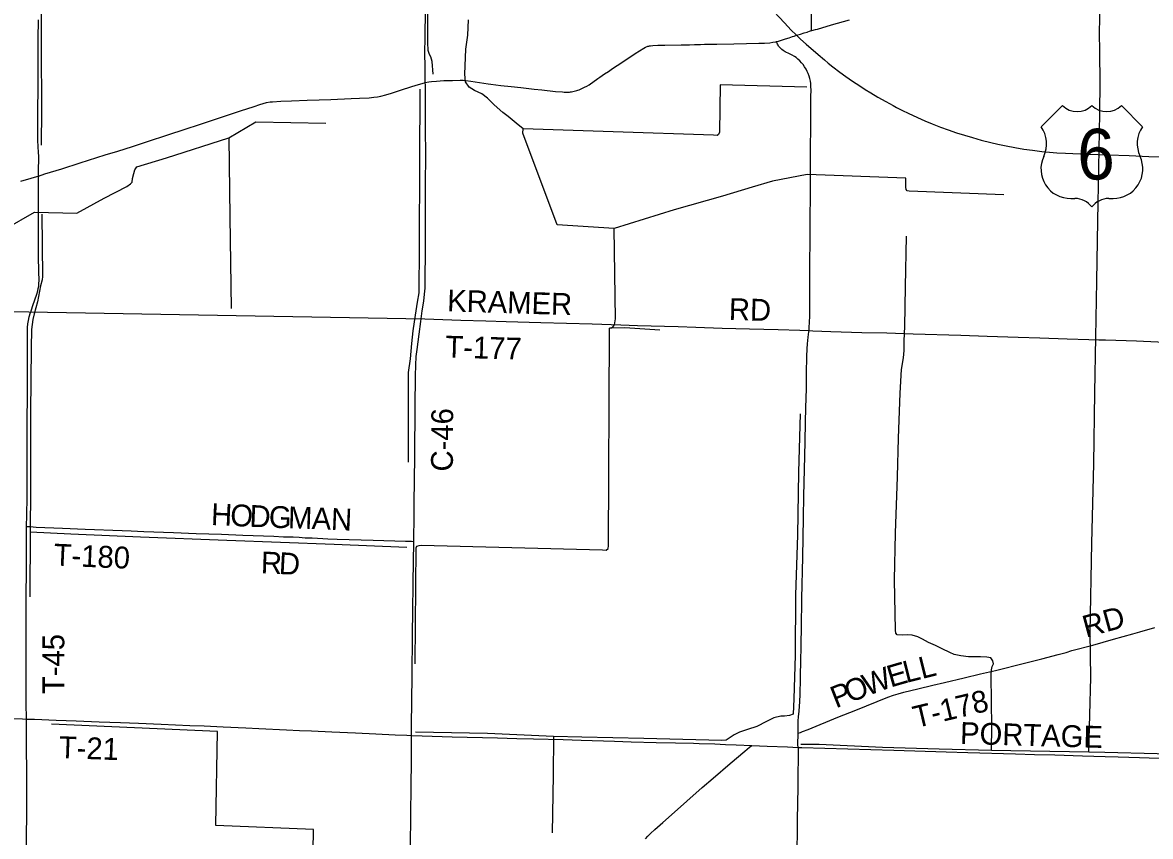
# Model space of a CAD drawing. Extents: x 0 to 680, y 0 to 834.
# Drawn here: x 187.9 to 300.6, y 223.2 to 304.5 of the extents above; entities that cross this region are included whole.
import ezdxf

# ---------------------------------------------------------------- set-up
doc = ezdxf.new("R2010")
doc.units = 0
for name, color, linetype in [('GM_X_County_Road', 7, 'Continuous'), ('GM_X_County_Road_Text', 7, 'Continuous'), ('GM_X_Minor_River', 7, 'Continuous'), ('GM_X_Township_Road', 7, 'Continuous'), ('GM_X_Township_Road_Text', 7, 'Continuous'), ('GM_X_US_Location', 7, 'Continuous'), ('GM_X_US_Route', 7, 'Continuous'), ('GM_X_US_Shield', 7, 'Continuous')]:
    doc.layers.add(name, color=color, linetype=linetype)

msp = doc.modelspace()

# ---------------------------------------------------------------- linework, layer by layer
at = {"layer": 'GM_X_County_Road'}
for points in [[(228.18, 298.27), (228.17, 298.53), (228.17, 298.79), (228.15, 299.46), (228.14, 300.18), (228.13, 301.37), (228.15, 303.16), (228.19, 305.66), (228.22, 309.12), (228.23, 310.91), (228.25, 314.73), (228.31, 320.34), (228.35, 323.92), (228.39, 326.54), (228.42, 328.93), (228.45, 332.36)], [(266.76, 303.71), (266.8, 303.72), (267.17, 303.82), (267.35, 303.87), (268.76, 304.28), (269.34, 304.44), (270.56, 304.78)], [(264.86, 303.11), (265.01, 303.17), (265.27, 303.25)], [(265.27, 303.25), (265.66, 303.37), (266.03, 303.48), (266.32, 303.57)], [(266.32, 303.57), (266.39, 303.6), (266.57, 303.65), (266.76, 303.71)], [(228.17, 298.53), (228.51, 298.58), (228.78, 298.63), (229.28, 298.67), (230.03, 298.71), (230.88, 298.74), (231.66, 298.75), (231.95, 298.75), (232.21, 298.73), (232.73, 298.66), (234.45, 298.4), (234.73, 298.36), (235.73, 298.23), (236.75, 298.12), (237.7, 298.02), (239.03, 297.87), (239.81, 297.79), (241.19, 297.64), (241.88, 297.58), (242.04, 297.56), (242.16, 297.56), (242.36, 297.56), (242.57, 297.57), (242.69, 297.58), (242.79, 297.6), (242.91, 297.62), (243.03, 297.65), (243.17, 297.68), (243.3, 297.73), (243.42, 297.76), (243.53, 297.8), (243.68, 297.86), (243.82, 297.92), (244.08, 298.05), (244.31, 298.17), (244.54, 298.31), (245.4, 298.91), (245.62, 299.06), (246.09, 299.38), (246.46, 299.64), (246.87, 299.92), (247.35, 300.24), (248.7, 301.13), (249.14, 301.43), (249.99, 301.96), (250.16, 302.04), (250.32, 302.11), (250.41, 302.15), (250.49, 302.17), (250.58, 302.19), (250.68, 302.2), (250.91, 302.22), (251.39, 302.24), (252.11, 302.25), (253.73, 302.28), (254.55, 302.3), (255.05, 302.32), (255.65, 302.33), (256.08, 302.34), (256.7, 302.35), (257.29, 302.36), (258.99, 302.39), (260.27, 302.41), (261.5, 302.44), (262.07, 302.45), (262.59, 302.5), (262.9, 302.54), (263.2, 302.6), (263.27, 302.61)], [(263.27, 302.61), (263.46, 302.66), (263.76, 302.75), (264.16, 302.88)], [(264.16, 302.88), (264.51, 302.99), (264.86, 303.11)], [(189.51, 289.18), (190.16, 289.39), (191.87, 289.92), (193.69, 290.49), (196.19, 291.3), (197.45, 291.68), (198.93, 292.15), (199.5, 292.33), (200.52, 292.66), (202.33, 293.26), (204.26, 293.9), (205.51, 294.3), (206.42, 294.6), (207.32, 294.9), (209.7, 295.69), (211.07, 296.13), (211.63, 296.33), (211.97, 296.44), (212.31, 296.52), (212.66, 296.58), (212.9, 296.6), (213.73, 296.65), (214.8, 296.69), (216.36, 296.75), (217.55, 296.8), (218.74, 296.84), (220.77, 296.92), (221.6, 296.96), (222.56, 297), (223.03, 297.05), (223.39, 297.1), (223.74, 297.17), (224.21, 297.28), (224.78, 297.45), (225.69, 297.75), (226.82, 298.13), (227.5, 298.34), (228.08, 298.5), (228.17, 298.53)], [(227.72, 274.66), (227.76, 274.93), (227.87, 275.73), (228.01, 276.68), (228.09, 277.39), (228.14, 277.99), (228.17, 278.58), (228.17, 279.54), (228.18, 280.97), (228.18, 281.92), (228.19, 283.59), (228.19, 284.07), (228.18, 284.55), (228.19, 285.14), (228.2, 286.81), (228.2, 288.13), (228.21, 291.47), (228.2, 293.73), (228.2, 295.05), (228.2, 295.88), (228.2, 296.84), (228.18, 298.27)], [(187.76, 288.66), (188.8, 288.96), (189.37, 289.13), (189.51, 289.18)], [(227.01, 252.42), (227.02, 252.69), (227.02, 253.13), (227.05, 254.92), (227.07, 256.59), (227.1, 258.74), (227.12, 261.24), (227.16, 266.14), (227.19, 269.24), (227.22, 270.31), (227.27, 271.15), (227.34, 271.86), (227.54, 273.4), (227.72, 274.66)], [(226.79, 233.07), (226.79, 233.32), (226.79, 234.27), (226.82, 236.78), (226.84, 239.28), (226.89, 243.34), (226.98, 250.86), (227.01, 252.42)], [(226.65, 196.73), (226.64, 197), (226.64, 197.27), (226.63, 199.18), (226.61, 200.97), (226.62, 203.36), (226.65, 207.65), (226.67, 210.52), (226.66, 213.74), (226.66, 214.93), (226.66, 216.61), (226.67, 219.59), (226.69, 222.34), (226.72, 225.2), (226.77, 228.42), (226.78, 230.57), (226.79, 232.96), (226.79, 233.07)]]:
    msp.add_lwpolyline(points, dxfattribs=at)
at = {"layer": 'GM_X_Minor_River'}
for points in [[(228.96, 299.35), (228.86, 300.64), (228.73, 301.09), (228.6, 301.34), (228.46, 301.73), (228.42, 302.53), (228.42, 313.14), (228.74, 324.28), (228.83, 333.5), (228.87, 343.1), (228.89, 347.61), (228.91, 352.15), (228.94, 355.48), (228.93, 357.36), (228.06, 357.4), (223.98, 357.49), (220.6, 357.57)], [(189.84, 314.17), (189.8, 309.14), (189.79, 302.09), (189.81, 295.76), (189.8, 292.27)], [(294.45, 231.64), (294.65, 239.1), (294.59, 243.59), (294.76, 252.52), (294.96, 260.45), (295.07, 267.55), (295.17, 273.08), (295.26, 278.7), (295.35, 284.71), (295.47, 290.05), (295.56, 295.43), (295.61, 298.58), (295.55, 301.5), (295.54, 303.62), (295.59, 306.02), (295.6, 308.36)], [(266.3, 298.07), (257.63, 298.28), (257.57, 293.55), (257.48, 293.34), (257.32, 293.24), (256.96, 293.26), (246.95, 293.6), (237.95, 293.91), (237.26, 294.48), (236.46, 295.14), (235.93, 295.54), (235.06, 296.31), (234.4, 296.97), (233.83, 297.38), (233.08, 297.74), (232.55, 298.06), (232.18, 298.58), (232.12, 299.37), (232.23, 301.87), (232.41, 303.27), (232.47, 304.8)], [(227.61, 297.87), (227.59, 290.69), (227.54, 282.11), (227.52, 277.52), (227.35, 276.58), (227.15, 275.29), (226.92, 273.73), (226.78, 272.47), (226.66, 270.94), (226.47, 269.55), (226.45, 260.6)], [(186.24, 283.92), (189.11, 285.56), (193.35, 285.48), (196.07, 286.99), (198.36, 288.15), (198.72, 288.4), (198.87, 288.58), (198.93, 288.93), (199.05, 289.44), (199.14, 289.82), (199.36, 290.1), (202.32, 291), (208.53, 292.99), (211.23, 294.6), (218.24, 294.48)], [(285.98, 287.31), (276.51, 287.67), (276.33, 287.71), (276.22, 287.83), (276.19, 288.06), (276.18, 288.98), (266.31, 289.34), (262.86, 288.67), (260.83, 288.07), (257.86, 287.19), (253.03, 285.8), (247.05, 283.94), (241.34, 284.3), (237.93, 293.48), (237.95, 293.91)], [(208.53, 292.99), (208.64, 285.11), (208.78, 275.94)], [(189.87, 285.39), (189.91, 279.14), (189.89, 278.82), (189.72, 278.21), (189.42, 276.63), (189.1, 275.41), (188.94, 274.87), (188.89, 274.36), (188.83, 273.85), (188.78, 272.03), (188.72, 265.56), (188.71, 257.88), (188.68, 253.65), (188.65, 247.17)], [(246.77, 274.02), (246.95, 274.15), (247.08, 274.33), (247.17, 274.92), (247.05, 283.94)], [(284.73, 231.8), (284.78, 234.23), (284.75, 236.63), (284.71, 239.37), (284.74, 239.86), (284.81, 240.19), (284.93, 240.47), (284.89, 240.76), (284.66, 241.05), (284.28, 241.14), (283.64, 241.17), (282.43, 241.15), (281.66, 241.25), (281, 241.41), (280.58, 241.6), (279.81, 241.97), (279.14, 242.29), (278.45, 242.6), (277.84, 242.94), (277.38, 243.16), (276.83, 243.34), (276.34, 243.35), (275.82, 243.33), (275.32, 243.37), (275.18, 243.52), (275.14, 243.81), (275.04, 248.84), (275.14, 253.52), (275.36, 259.15), (275.44, 263), (275.63, 267.51), (275.76, 269.85), (275.96, 271.04), (276.01, 271.76), (276.03, 272.72), (276.07, 274.15), (276.16, 278.13), (276.26, 283.19)], [(227.15, 240.45), (227.27, 252.06), (227.33, 252.22), (227.56, 252.29), (227.75, 252.31), (245.89, 251.86), (246.24, 251.83), (246.43, 251.98), (246.48, 252.25), (246.57, 273.7), (246.57, 273.99), (246.64, 274.02), (246.77, 274.02), (248.09, 274.07), (251.61, 273.81)], [(265.62, 265.44), (265.47, 259.62), (265.36, 253.31), (265.15, 247.34), (265.12, 241.32), (264.99, 236.97), (264.93, 235.42), (264.56, 235.29), (264.07, 235.24), (263.69, 235.22), (262.99, 235.08), (262.26, 234.69), (261.28, 234.22), (260.35, 233.91), (259.57, 233.65), (259.02, 233.37), (258.22, 232.85), (257.81, 232.82), (250.01, 232.99), (243.81, 233.14), (240.98, 233.22), (234.4, 233.5), (227.19, 233.65)], [(188.68, 253.65), (192.75, 253.46), (199.7, 253.16), (208.35, 252.82), (219.06, 252.41), (226.31, 252.12)], [(328.62, 238.69), (328.67, 234.36), (328.71, 230.59), (323.47, 230.8), (316.16, 231.05), (308.68, 231.28), (304.59, 231.37), (301.3, 231.48), (296.08, 231.6), (294.45, 231.64), (284.73, 231.8), (279.51, 231.95), (273.85, 232.09), (267.51, 232.41), (265.69, 232.42)], [(225.69, 156.4), (225.77, 161.71), (225.82, 168.08), (225.67, 173.03), (225.8, 175.83), (226.05, 186.97), (226.14, 191.99), (226.1, 194.92), (226.09, 209.74), (226.16, 218.33), (226.11, 218.56), (225.98, 218.74), (225.77, 218.78), (224.97, 218.81), (217.54, 219.1), (217.23, 219.13), (217.09, 219.21), (216.94, 219.61), (217, 223.9), (207.23, 224.33), (207.42, 233.72), (190.81, 234.44)], [(240.98, 233.22), (240.94, 229.35), (240.85, 223.59)]]:
    msp.add_lwpolyline(points, dxfattribs=at)
at = {"layer": 'GM_X_Township_Road'}
msp.add_line((188.74, 275.6), (188.91, 276.14), dxfattribs=at)
for points in [[(266.76, 303.71), (266.76, 303.9), (266.76, 305.17), (266.78, 306.5), (266.78, 307.62), (266.78, 308.43), (266.8, 310.44), (266.81, 312.08)], [(189.51, 289.18), (189.51, 289.39), (189.52, 289.86), (189.55, 290.82), (189.55, 291.18), (189.53, 291.53), (189.48, 292.13), (189.45, 292.72), (189.45, 293.44), (189.47, 295.23), (189.48, 298.46), (189.49, 302.88), (189.51, 304.79)], [(264.86, 303.11), (265.01, 303.17), (265.27, 303.25)], [(265.27, 303.25), (265.66, 303.37), (266.03, 303.48), (266.32, 303.57)], [(266.32, 303.57), (266.39, 303.6), (266.57, 303.65), (266.76, 303.71)], [(263.27, 302.61), (263.46, 302.66), (263.76, 302.75), (264.16, 302.88)], [(266.7, 297.19), (266.71, 297.7), (266.69, 298.19), (266.68, 298.43), (266.64, 298.66), (266.59, 298.92), (266.51, 299.17), (266.43, 299.42), (266.33, 299.64), (266.21, 299.87), (266.07, 300.1), (265.92, 300.31), (265.76, 300.49), (265.59, 300.68), (265.39, 300.86), (265.21, 301.01), (265.05, 301.12), (264.83, 301.26), (264.55, 301.4), (264.14, 301.6), (263.94, 301.72), (263.78, 301.83), (263.65, 301.94), (263.56, 302.04), (263.47, 302.16), (263.41, 302.26), (263.37, 302.37), (263.27, 302.61)], [(264.16, 302.88), (264.51, 302.99), (264.86, 303.11)], [(266.51, 273.75), (266.53, 274.07), (266.55, 274.6), (266.58, 275.2), (266.59, 275.79), (266.6, 277.6), (266.6, 280.45), (266.62, 282.77), (266.63, 284.2), (266.66, 287.99), (266.66, 290), (266.66, 291), (266.67, 292.41), (266.68, 293.61), (266.68, 294.7), (266.69, 296.61), (266.7, 297.19)], [(188.91, 276.14), (188.95, 276.25), (189.35, 277.37), (189.45, 277.72), (189.5, 277.95), (189.55, 278.18), (189.57, 278.42), (189.58, 278.78), (189.57, 279.61), (189.53, 281.17), (189.53, 282.48), (189.52, 285.34), (189.52, 287.61), (189.51, 288.81), (189.51, 289.18)], [(111.24, 276.97), (228.13, 274.92), (231.71, 274.79), (234.22, 274.71), (236.24, 274.65), (239.71, 274.55), (244.84, 274.41), (247.7, 274.32), (249.37, 274.27), (253.42, 274.14), (255.21, 274.08), (257.83, 273.99), (260.57, 273.91), (263.44, 273.84), (265.58, 273.78), (266.51, 273.75)], [(188.33, 254.19), (188.35, 255.31), (188.38, 257.1), (188.39, 259.37), (188.4, 260.92), (188.4, 262.59), (188.4, 264.98), (188.41, 267.01), (188.42, 269.99), (188.41, 272.38), (188.41, 273.45), (188.43, 274.05), (188.46, 274.41), (188.51, 274.76), (188.59, 275.11), (188.72, 275.57), (188.74, 275.6)], [(265.41, 233.55), (265.42, 233.59), (265.43, 234.31), (265.44, 234.76), (265.47, 235.16), (265.53, 235.73), (265.57, 236.23), (265.59, 236.68), (265.62, 237.45), (265.65, 238.97), (265.7, 241.05), (265.72, 241.86), (265.73, 242.74), (265.75, 243.84), (265.76, 244.87), (265.79, 246.18), (265.8, 246.99), (265.88, 251.12), (265.96, 255.05), (266, 257.23), (266.06, 259.86), (266.11, 262.63), (266.16, 264.59), (266.19, 266.04), (266.24, 267.97), (266.27, 269.48), (266.29, 271.17), (266.32, 271.91), (266.36, 272.44), (266.42, 273.08), (266.5, 273.62), (266.51, 273.75)], [(266.51, 273.75), (266.9, 273.73), (268.69, 273.67), (271.79, 273.57), (274.29, 273.51), (276.92, 273.43), (281.69, 273.28), (284.31, 273.2), (287.42, 273.1), (289.56, 273.03), (292.31, 272.94), (294.45, 272.87), (295.46, 272.84)], [(295.46, 272.84), (296.12, 272.81), (299.22, 272.71), (301.37, 272.64), (302.92, 272.59), (304.95, 272.5), (305.2, 272.5)], [(188.31, 234.95), (188.31, 235.02), (188.3, 236.45), (188.3, 238.96), (188.29, 243.13), (188.3, 247.55), (188.32, 249.46), (188.33, 251.85), (188.32, 253.76), (188.33, 254.19)], [(188.33, 254.19), (188.69, 254.17), (189.29, 254.13), (191.91, 254.02), (194.18, 253.93), (197.88, 253.78), (198.77, 253.74)], [(198.77, 253.74), (200.03, 253.69), (203.02, 253.59), (205.29, 253.49), (207.8, 253.4), (209.94, 253.32), (213.05, 253.21), (214, 253.16), (214.96, 253.14), (215.55, 253.1), (216.15, 253.06), (216.87, 253.04), (217.94, 252.98), (218.42, 252.96), (219.37, 252.93), (222.96, 252.8), (226.18, 252.7), (226.66, 252.7), (226.8, 252.7), (227.02, 252.69)], [(265.41, 233.55), (265.64, 233.62), (265.86, 233.7), (266.42, 233.91), (269.4, 235.13), (271.17, 235.85), (274.39, 237.13), (274.95, 237.34), (275.4, 237.48), (275.98, 237.64), (277.37, 237.98), (278.88, 238.32), (280.04, 238.6), (282.02, 239.06), (283.64, 239.46), (285.15, 239.81), (288.05, 240.52), (289.78, 240.97), (291.4, 241.41), (292.2, 241.61), (292.78, 241.78), (294.85, 242.33), (296.92, 242.92), (298.87, 243.46), (299.56, 243.65), (301.05, 244.1)], [(149.45, 236.02), (150.22, 235.98), (153.57, 235.88), (158.1, 235.78), (161.8, 235.68), (163.71, 235.63), (168.13, 235.52), (171.59, 235.42), (173.26, 235.37), (175.41, 235.31), (179.34, 235.2), (181.61, 235.15), (186.62, 235), (187.94, 234.96), (188.31, 234.95)], [(188.15, 196.36), (188.15, 196.7), (188.17, 198.13), (188.17, 200.16), (188.21, 203.74), (188.27, 207.2), (188.29, 209.11), (188.32, 210.9), (188.31, 213.77), (188.31, 215.56), (188.3, 217.59), (188.3, 219.26), (188.31, 220.81), (188.31, 222.72), (188.34, 225.94), (188.35, 227.5), (188.35, 229.88), (188.33, 231.91), (188.32, 233.46), (188.31, 234.95)], [(188.31, 234.95), (189.13, 234.92), (191.28, 234.84), (193.3, 234.77), (195.57, 234.68), (196.65, 234.65), (197.72, 234.61), (199.51, 234.54), (201.77, 234.45), (204.64, 234.31), (206.07, 234.26), (207.98, 234.17), (210.24, 234.06), (211.55, 234), (214.3, 233.88), (215.61, 233.81), (216.8, 233.76), (218.83, 233.67), (221.21, 233.56), (223.24, 233.48), (225.15, 233.38), (226.34, 233.34), (226.79, 233.32)], [(226.79, 233.32), (227.87, 233.28), (230.86, 233.18), (235.39, 233.07), (237.3, 233.02), (238.97, 232.96), (241.95, 232.89), (243.74, 232.83), (247.08, 232.73), (248.74, 232.67), (251.25, 232.62), (253.16, 232.57), (254.95, 232.53), (255.54, 232.51), (257.09, 232.46), (258.17, 232.4), (259.24, 232.36), (260.79, 232.32)], [(265.43, 232.12), (265.41, 232.22), (265.4, 232.28), (265.4, 232.32), (265.4, 232.36), (265.41, 233.55)], [(250.17, 222.99), (250.41, 223.25), (250.66, 223.51), (251.09, 223.92), (251.89, 224.63), (253.06, 225.66), (254.31, 226.76), (255.83, 228.11), (256.92, 229.04), (258.64, 230.52), (260.1, 231.75), (260.56, 232.13), (260.79, 232.32)], [(260.79, 232.32), (262.34, 232.25), (264.36, 232.16), (265.43, 232.12)], [(265.32, 222.02), (265.35, 223.62), (265.37, 224.84), (265.4, 226.56), (265.41, 228.11), (265.44, 229.83), (265.46, 230.64), (265.47, 231.54), (265.47, 231.93), (265.47, 231.96), (265.46, 231.99), (265.46, 232.02), (265.43, 232.12)], [(265.43, 232.12), (265.79, 232.11), (274.98, 231.83), (280.22, 231.66), (282.37, 231.61), (287.14, 231.48), (289.05, 231.42), (291.08, 231.36), (293.82, 231.27), (296.09, 231.2), (297.4, 231.17), (299.54, 231.11), (300.5, 231.08), (301.69, 231.05), (304.08, 230.97), (304.45, 230.96)]]:
    msp.add_lwpolyline(points, dxfattribs=at)
at = {"layer": 'GM_X_US_Route'}
for points in [[(262.5, 306.15), (264.07, 304.48), (264.74, 303.77), (265.21, 303.3), (265.27, 303.25)], [(265.27, 303.25), (265.66, 302.87), (266.23, 302.36), (267.42, 301.31), (268.04, 300.78), (268.42, 300.47), (268.88, 300.1), (269.6, 299.55), (270.2, 299.11), (270.84, 298.67), (271.58, 298.18), (272.13, 297.83), (272.67, 297.5), (273.39, 297.07), (274.17, 296.62), (274.91, 296.22), (275.26, 296.04), (275.86, 295.74), (276.42, 295.46), (277.35, 295.03), (278.07, 294.71), (278.82, 294.39), (279.64, 294.07), (280.42, 293.79), (281.24, 293.51), (282.03, 293.26), (282.83, 293.02), (283.71, 292.78), (284.66, 292.54), (285.38, 292.37), (286.19, 292.2), (287.08, 292.03), (287.98, 291.88), (288.83, 291.76), (289.77, 291.64), (290.53, 291.57), (291.27, 291.51), (292.15, 291.46), (294.37, 291.37), (296.4, 291.29), (298.5, 291.22), (300.45, 291.14), (301.79, 291.09)]]:
    msp.add_lwpolyline(points, dxfattribs=at)
at = {"layer": 'GM_X_US_Shield'}
for p, q in [((291.82, 296.22), (289.71, 294.11)), ((299.83, 294.11), (297.73, 296.22)), ((292.66, 286.94), (293.08, 286.94)), ((296.46, 286.94), (296.88, 286.94))]:
    msp.add_line(p, q, dxfattribs=at)
for centre, radius, start, end in [((293.3, 297.73), 2.11, 225.573, 314.427), ((296.25, 297.73), 2.11, 225.573, 314.427), ((287.29, 292.42), 2.95, 334.5471, 35.0009), ((302.25, 292.42), 2.95, 144.9991, 205.4529), ((292.63, 289.89), 2.95, 154.8319, 270.6383), ((296.91, 289.89), 2.95, 269.3617, 25.1681), ((293.08, 284.83), 2.11, 36.8699, 90), ((296.46, 284.83), 2.11, 90, 143.1301)]:
    msp.add_arc(centre, radius, start, end, dxfattribs=at)

# ---------------------------------------------------------------- texts
at = {"layer": 'GM_X_County_Road_Text'}
msp.add_text('C-46', height=2.182, rotation=89.6587, dxfattribs=at).set_placement((230.92, 259.67))
at = {"layer": 'GM_X_Township_Road_Text'}
for s, height, rotation, p in [('KRAMER', 2.182, 358.2397, (230.33, 275.67)), ('RD', 2.182, 358.5193, (258.48, 274.81)), ('T-177', 2.182, 358.3265, (230.15, 271.06)), ('H', 2.18, 357.5003, (206.73, 254.33)), ('O', 2.18, 357.4967, (208.65, 254.24)), ('D', 2.18, 357.5024, (210.57, 254.16)), ('G', 2.18, 358.024, (212.51, 254.07)), ('M', 2.18, 358.1903, (214.43, 254.01)), ('A', 2.18, 357.6388, (216.79, 253.93)), ('N', 2.18, 357.6315, (218.71, 253.85)), ('T-180', 2.182, 357.4726, (191, 250.29)), ('R', 2.18, 358.2239, (211.72, 249.5)), ('D', 2.18, 356.9933, (213.5, 249.44)), ('RD', 2.182, 15.2121, (294.18, 243.07)), ('T-45', 2.182, 90, (192.1, 237.44)), ('L', 2.18, 14.0383, (277.79, 238.94)), ('W', 2.18, 20.1211, (272.33, 237.23)), ('E', 2.18, 16.1685, (274.66, 238.09)), ('L', 2.18, 14.1308, (276.21, 238.54)), ('O', 2.18, 21.5099, (270.56, 236.53)), ('P', 2.18, 21.512, (269.19, 236)), ('T-178', 2.182, 13.3683, (277.19, 234.04)), ('PORTAGE', 2.182, 358.3556, (281.58, 232.47)), ('T-21', 2.182, 357.8808, (191.52, 231.06))]:
    msp.add_text(s, height=height, rotation=rotation, dxfattribs=at).set_placement(p)
at = {"layer": 'GM_X_US_Location'}
for s in ['0', '/']:
    msp.add_text(s, height=0.00727, dxfattribs=at).set_placement((299.45, 291.18))
msp.add_text('6', height=0.00727, rotation=0, dxfattribs=at).set_placement((298.72, 289.67))
at = {"layer": 'GM_X_US_Shield'}
msp.add_text('6', height=5.06, dxfattribs=at).set_placement((293.3, 288.84))

doc.saveas('drawing.dxf')
